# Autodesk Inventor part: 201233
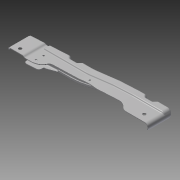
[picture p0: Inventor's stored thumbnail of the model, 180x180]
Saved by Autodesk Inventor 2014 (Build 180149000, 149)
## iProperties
Created: 2007-12
Part Number: 201233
Document SubType Name: Modeling
Designer: MM
Density: 7.85 g/cm^3
Mass: 1039.32 g
Surface Area: 1235.29 cm^2
Volume: 132.397 cm^3
Material: Steel
Description: TOP LEFT SIDE PLATE
Appearance: Steel
Component Category: Lower Component
Author: MM
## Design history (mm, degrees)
node "D-D201009" dims "d0" = 10
  workplane "Work Plane1"
body "Solid1"
tag "TaggingFeature2"
workplane "Work Plane2"
feature "DerivedBody::D-D201009" dims "d0" = 10
